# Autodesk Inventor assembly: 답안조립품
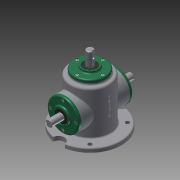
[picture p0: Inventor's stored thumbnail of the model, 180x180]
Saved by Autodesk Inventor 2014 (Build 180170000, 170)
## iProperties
Created: 2018-04
Part Number: 답안조립품
Document SubType Name: Assembly
Designer: net
Author: net
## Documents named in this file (16)
- C:\Users\net\Desktop\480407V1016\답안조립품.iam
- C:\Users\net\Desktop\480407V1016\본체.ipt
- C:\Users\net\Desktop\480407V1016\메인 축.ipt
- 메인 축.ipt
- C:\Users\net\Desktop\480407V1016\메인 베벨기어.ipt
- C:\Users\net\Desktop\480407V1016\키 5x5.ipt
- C:\Users\net\Desktop\480407V1016\베어링 6203.ipt
- C:\Users\net\Desktop\480407V1016\커버.ipt
- C:\Users\net\Desktop\480407V1016\오일 실.ipt
- 오일 실.ipt
- C:\Users\net\Desktop\480407V1016\서브 축.ipt
- 서브 축.ipt
- C:\Users\net\Desktop\480407V1016\서브 베벨기어.ipt
- C:\Users\net\Desktop\480407V1016\키 4x4.ipt
- C:\Users\net\Desktop\480407V1016\볼트 M4.ipt
- 볼트 M4.ipt
